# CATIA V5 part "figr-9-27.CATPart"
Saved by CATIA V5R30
Part number: Part1
Bounding box of the stored display mesh (mm): x -75 to 75, y -50 to 50, z 0 to 40
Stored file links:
  D:\PROJECTS\CATIA V56R 2020\Resources\Parts File\c09_catia_v5_6r2020_prt\figr-9-27.CATPart
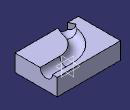
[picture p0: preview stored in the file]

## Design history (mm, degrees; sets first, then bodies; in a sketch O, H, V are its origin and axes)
Body1 (main body)
  Sketch1 on xy-plane, origin (0, 0, 0), H (1, 0, 0), V (0, 1, 0)
    line L1 (-75, 50) -> (75, 50)
    line L2 (75, 50) -> (75, -50)
    line L3 (75, -50) -> (-75, -50)
    line L4 (-75, -50) -> (-75, 50)
    axis line L5 (75, -50) -> (-75, 50)
    length L2 = 100
    length L3 = 150
    horizontal: L1 H, L3 H
    vertical: L2 V, L4 V
    midpoint: O L5
  Pad1: profile Sketch1, direction (0, 0, 1), length 40
  Sketch2 on face of Pad1, origin (75, 0, 0), H (0, 1, 0), V (0, 0, 1)
    arc A1 centre (24.1478, 40) radius 14.6047 from (9.543, 40) to (38.7525, 40) ccw
    point P1 (24.1478, 40)
    reference projected point E1 (24.1478, 40) from vertex of Sketch3
    line L1 (9.543, 40) -> (38.7525, 40)
    coincidence: P1 E1
    horizontal: L1 H
  Sketch3 on face of Pad1, origin (0, 0, 40), H (1, 0, 0), V (0, 1, 0)
    point P1 (75, 24.1478)
    line L1 (75, 24.1478) -> (28.6577, 24.1478)
    arc A1 centre (28.6577, -39.2062) radius 63.354 from (28.6577, 24.1478) to (-33.8383, -28.8149) ccw
    arc A2 centre (-62.192, -24.1005) radius 28.7429 from (-33.8383, -28.8149) to (-49.7271, -50) cw
    point P6 (-49.7271, -50)
    reference projected line E1 (75, -50) -> (75, 50) from edge [face of Pad1 | face of Pad1]
    reference projected line E2 (-75, -50) -> (75, -50) from edge [face of Pad1 | face of Pad1]
    horizontal: L1 H
    tangency: A1 L1, A2 A1
    coincidence: P1 E1, P6 E2
  Slot1: profile Sketch2, centre curve Sketch3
